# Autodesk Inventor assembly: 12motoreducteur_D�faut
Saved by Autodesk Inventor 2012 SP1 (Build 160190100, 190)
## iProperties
Created: 2011-01
Part Number: 12motoreducteur_D�faut
Document SubType Name: Assembly
Designer: eric
Mass: 915.076 g
Surface Area: 3343.24 cm^2
Volume: 915.076 cm^3
Density: 1 g/cm^3
Author: eric
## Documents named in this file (12)
- D:\Cours\Inventor salle SI\chariot_de_golf_2008\chariot_de_golf_trolem\12motoreducteur_Defaut.iam
- D:\Cours\Inventor salle SI\chariot_de_golf_2008\chariot_de_golf_trolem\12Ecrou_freineM5.ipt
- D:\Cours\Inventor salle SI\chariot_de_golf_2008\chariot_de_golf_trolem\12VisCHC M5-20_Defaut.ipt
- D:\Cours\Inventor salle SI\chariot_de_golf_2008\chariot_de_golf_trolem\12Roulement_BC17x40x12_Defaut.iam
- D:\Cours\Inventor salle SI\chariot_de_golf_2008\chariot_de_golf_trolem\tube_Defaut.ipt
- D:\Cours\Inventor salle SI\chariot_de_golf_2008\chariot_de_golf_trolem\12VisCHC M5-55_Defaut.ipt
- D:\Cours\Inventor salle SI\chariot_de_golf_2008\chariot_de_golf_trolem\12Roulement_BC8x22x7_Defaut.iam
- D:\Cours\Inventor salle SI\chariot_de_golf_2008\chariot_de_golf_trolem\12VisCHC M5-16_Defaut.ipt
- D:\Cours\Inventor salle SI\chariot_de_golf_2008\chariot_de_golf_trolem\12coquille_gauche_Defaut.ipt
- D:\Cours\Inventor salle SI\chariot_de_golf_2008\chariot_de_golf_trolem\12coquille_droite_Defaut.ipt
- D:\Cours\Inventor salle SI\chariot_de_golf_2008\chariot_de_golf_trolem\12moteur_Defaut.ipt
- D:\Cours\Inventor salle SI\chariot_de_golf_2008\chariot_de_golf_trolem\12joint_etancheite_Defaut.ipt
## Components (35 placed, 11 different names)
1. 12Ecrou_freineM5:1
2. 12Ecrou_freineM5:2
3. 12VisCHC M5-20_Defaut:1
4. 12Roulement_BC17x40x12_Defaut:1 [sub-assembly]
5. 12Ecrou_freineM5:3
6. 12VisCHC M5-20_Defaut:2
7. 12VisCHC M5-20_Defaut:3
8. tube_Defaut:1
9. 12Ecrou_freineM5:4
10. 12VisCHC M5-20_Defaut:4
11. 12VisCHC M5-20_Defaut:5
12. 12Ecrou_freineM5:5
13. 12VisCHC M5-20_Defaut:6
14. 12Ecrou_freineM5:6
15. 12Ecrou_freineM5:7
16. 12VisCHC M5-55_Defaut:1
17. 12Roulement_BC17x40x12_Defaut:2 [sub-assembly]
18. 12Roulement_BC8x22x7_Defaut:1 [sub-assembly]
19. 12VisCHC M5-16_Defaut:1
20. 12Ecrou_freineM5:8
21. 12VisCHC M5-20_Defaut:7
22. 12coquille_gauche_Defaut:1
23. 12coquille_droite_Defaut:1
24. 12Ecrou_freineM5:9
25. 12Ecrou_freineM5:10
26. 12VisCHC M5-20_Defaut:8
27. 12moteur_Defaut:1
28. 12Ecrou_freineM5:11
29. 12Ecrou_freineM5:12
30. 12VisCHC M5-20_Defaut:9
31. 12VisCHC M5-16_Defaut:2
32. 12joint_etancheite_Defaut:1
33. 12Roulement_BC8x22x7_Defaut:2 [sub-assembly]
34. 12VisCHC M5-20_Defaut:10
35. 12Ecrou_freineM5:13
